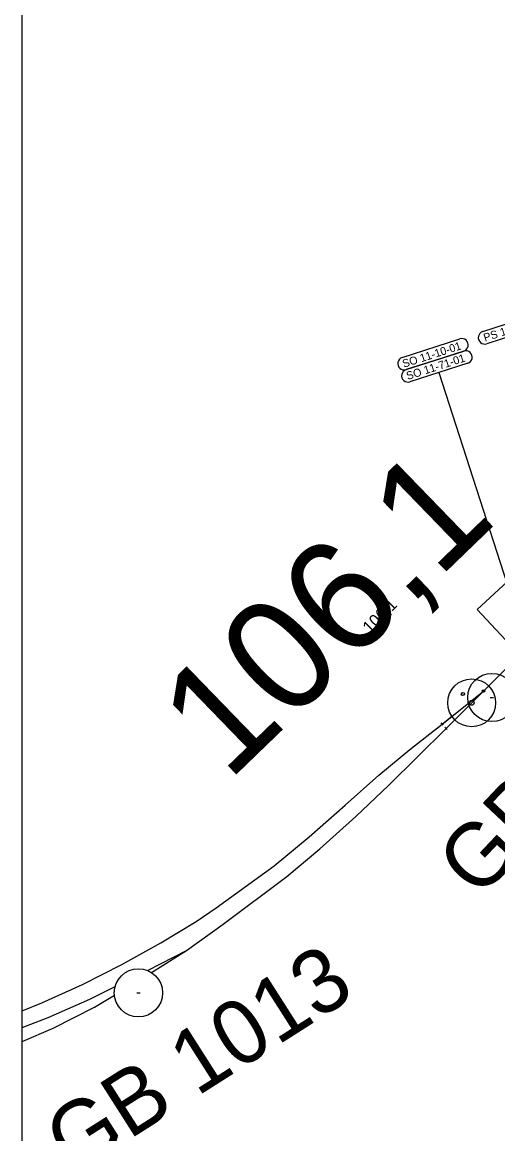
# Model space of a CAD drawing. Extents: x -759005 to -757278, y -1175311 to -1173953.
# Drawn here: x -758600 to -758451.1, y -1175031.8 to -1174683.4 of the extents above; entities that cross this region are included whole.
import ezdxf

# ---------------------------------------------------------------- set-up
doc = ezdxf.new("R2010")
doc.units = 0
for name, color, linetype in [('_NOR-popis', 7, 'Continuous'), ('G_Obvod stavby', 7, 'Continuous'), ('Vrstva 1', 7, 'Continuous'), ('Vrstva 12', 7, 'Continuous'), ('Vrstva 2', 7, 'Continuous'), ('Vrstva 52', 7, 'Continuous'), ('Vrstva 53', 7, 'Continuous'), ('Vrstva 62', 7, 'Continuous'), ('Vrstva 7', 7, 'Continuous')]:
    doc.layers.add(name, color=color, linetype=linetype)

# ---------------------------------------------------------------- blocks, each defined once
blk = doc.blocks.new('C093_1_1')
at = {"layer": 'Vrstva 7'}
blk.add_line((-0.05, 0), (0.05, 0), dxfattribs=at)
blk.add_circle((0, 0), 0.5, dxfattribs=at)
blk = doc.blocks.new('C513_1_1')
at = {"layer": 'Vrstva 7'}
blk.add_circle((0, 0), 0.75, dxfattribs=at)
blk = doc.blocks.new('C084')
at = {"layer": 'Vrstva 2'}
blk.add_line((0, 0.5), (0, -0.5), dxfattribs=at)
blk = doc.blocks.new('C083')
at = {"layer": 'Vrstva 2'}
blk.add_circle((0, 0), 0.4, dxfattribs=at)

msp = doc.modelspace()

# ---------------------------------------------------------------- linework, layer by layer
at = {"layer": '_NOR-popis'}
for points in [[(-758455.82, -1174780.33), (-758437.73, -1174774.5)], [(-758445.55, -1174781.22), (-758454.59, -1174784.13)], [(-758481.06, -1174788.46), (-758462.97, -1174782.63)], [(-758479.83, -1174792.26), (-758461.75, -1174786.44)], [(-758461.75, -1174786.44), (-758470.79, -1174789.35)], [(-758470.79, -1174789.35), (-758479.83, -1174792.26)], [(-758460.52, -1174790.25), (-758469.56, -1174793.16), (-758441.83, -1174879.27)], [(-758469.56, -1174793.16), (-758478.61, -1174796.07)]]:
    msp.add_lwpolyline(points, dxfattribs=at)
for centre, start, end in [((-758455.21, -1174782.23), 107.854, 287.8547), ((-758462.36, -1174784.53), 287.8533, 107.854), ((-758480.45, -1174790.36), 107.854, 287.8547), ((-758461.13, -1174788.34), 287.8533, 107.854), ((-758479.22, -1174794.17), 107.854, 287.8547)]:
    msp.add_arc(centre, 2, start, end, dxfattribs=at)
at = {"layer": 'G_Obvod stavby'}
for points in [[(-758424.37, -1174835.44), (-758423.81, -1174836.28), (-758457.56, -1174867.46)], [(-758457.56, -1174867.46), (-758444.33, -1174881.69), (-758438.77, -1174887.67), (-758435.38, -1174884.05), (-758431.98, -1174880.42), (-758414.84, -1174864.78), (-758400.07, -1174851.38)]]:
    msp.add_lwpolyline(points, dxfattribs=at)
at = {"layer": 'Vrstva 1'}
for p, q in [((-758539.25, -1174960.98), (-758521.11, -1174947.78)), ((-758537.07, -1174966.08), (-758517.15, -1174951.13))]:
    msp.add_line(p, q, dxfattribs=at)
for points in [[(-758478.65, -1174911.36), (-758468.54, -1174903.34), (-758455.58, -1174892.99), (-758444.94, -1174882.37), (-758443.82, -1174881.25)], [(-758476.15, -1174913.53), (-758467.31, -1174904.71), (-758455.58, -1174892.99), (-758444.94, -1174882.37), (-758443.82, -1174881.25)], [(-758521.11, -1174947.78), (-758510.14, -1174938.7), (-758498.94, -1174928.75), (-758488.41, -1174919.4), (-758478.65, -1174911.36), (-758468.54, -1174903.34), (-758465.5, -1174900.91)], [(-758517.15, -1174951.13), (-758506.8, -1174942.49), (-758495.54, -1174932.34), (-758485.33, -1174922.6), (-758476.15, -1174913.53), (-758467.31, -1174904.71), (-758464.6, -1174902)], [(-758600, -1174993.2), (-758593.86, -1174990.73), (-758581.15, -1174984.98), (-758568.83, -1174978.75), (-758556.64, -1174971.96), (-758545.59, -1174965.22), (-758539.25, -1174960.98)], [(-758560.82, -1174980.59), (-758548.53, -1174974.37), (-758537.07, -1174966.08)], [(-758559.51, -1174981.26), (-758548.53, -1174974.37), (-758537.07, -1174966.08)], [(-758600, -1174998.43), (-758591.88, -1174995.3), (-758578.84, -1174989.58), (-758570.93, -1174985.65)], [(-758600, -1175002.81), (-758590.35, -1174998.63), (-758577.43, -1174992.1), (-758571.15, -1174988.36)]]:
    msp.add_lwpolyline(points, dxfattribs=at)
at = {"layer": 'Vrstva 12'}
msp.add_circle((-758459.29, -1174896.7), 7.5, dxfattribs=at)
at = {"layer": 'Vrstva 2'}
msp.add_line((-758468.54, -1174903.34), (-758455.58, -1174892.99), dxfattribs=at)
msp.add_lwpolyline([(-758467.31, -1174904.71), (-758455.58, -1174892.99), (-758444.94, -1174882.37), (-758443.82, -1174881.25)], dxfattribs=at)
at = {"layer": 'Vrstva 52'}
for p, q in [((-758453.46, -1174895.02), (-758452.46, -1174895.02)), ((-758564.12, -1174987.6), (-758563.12, -1174987.6))]:
    msp.add_line(p, q, dxfattribs=at)
for centre in [(-758452.96, -1174895.02), (-758563.62, -1174987.6)]:
    msp.add_circle(centre, 7.56, dxfattribs=at)
at = {"layer": 'Vrstva 62'}
msp.add_lwpolyline([(-758600, -1174500), (-758100, -1174500), (-758100, -1175200), (-758600, -1175200), (-758600, -1174500)], dxfattribs=at)
msp.add_lwpolyline([(-758600, -1174500), (-758100, -1174500), (-758100, -1175200), (-758600, -1175200), (-758600, -1174500)], dxfattribs=at)

# ---------------------------------------------------------------- block references
at = {"layer": 'Vrstva 2'}
for name, p, rotation in [('C083', (-758455.58, -1174892.99), -135.035039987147), ('C084', (-758468.54, -1174903.34), -141.38874749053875), ('C084', (-758467.31, -1174904.71), -135.03420351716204)]:
    msp.add_blockref(name, p, dxfattribs=dict(at, rotation=rotation))
at = {"layer": 'Vrstva 7'}
for name, p, rotation in [('C093_1_1', (-758462.04, -1174893.94), 45.09010786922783), ('C513_1_1', (-758459.29, -1174896.7), 44.968259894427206)]:
    msp.add_blockref(name, p, dxfattribs=dict(at, rotation=rotation))

# ---------------------------------------------------------------- texts
at = {"layer": '_NOR-popis'}
for s, p in [('PS 11-01-31', (-758455.11, -1174783.51)), ('SO 11-10-01', (-758480.53, -1174791.7)), ('SO 11-71-01', (-758479.31, -1174795.51))]:
    msp.add_text(s, height=2.5, rotation=17.854, dxfattribs=at).set_placement(p)
at = {"layer": 'Vrstva 53'}
for s, rotation, p in [('GB 1014', 46.733, (-758457.03, -1174958.56)), ('GB 1013', 32.471, (-758584.19, -1175044.98))]:
    msp.add_text(s, height=20, rotation=rotation, dxfattribs=at).set_placement(p)
at = {"layer": 'Vrstva 62'}
msp.add_text('106,1', height=35.174, rotation=44.0539, dxfattribs=at).set_placement((-758535.55, -1174921.65))
at = {"layer": 'Vrstva 7'}
msp.add_text('106,1', height=3.75, rotation=44.9683, dxfattribs=at).set_placement((-758491.2, -1174875.13))

doc.saveas('drawing.dxf')
